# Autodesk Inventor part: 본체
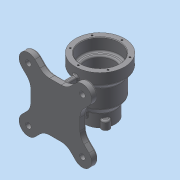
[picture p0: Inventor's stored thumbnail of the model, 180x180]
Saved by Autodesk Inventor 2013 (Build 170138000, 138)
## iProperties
Created: 2017-03
Part Number: 본체
Material: 일반
Document SubType Name: Modeling
Designer: dgall
Density: 1 g/cm^3
Author: dgall
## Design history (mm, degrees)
sketch "스케치1"
  geometry: L1 (0, 50)-(0, -50); L2 (35, 50)-(35, 27); L3 (35, 27)-(26, 27); L4 (26, 27)-(26, -20); L5 (26, -20)-(17.5, -20); L6 (17.5, -20)-(17.5, -50); L7 (17.5, -50)-(27.5, -50); L8 (27.5, -50)-(27.5, -27); L9 (27.5, -27)-(36, -15); L10 (36, -15)-(36, 19); L11 (36, 19)-(45, 30); L12 (45, 30)-(45, 50); L13 (45, 50)-(35, 50); 2 further points
  constraints: 26 end point, 9 parallel, 2 horizontal alignment, 1 coincident, 1 midpoint, 1 perpendicular, 1 vertical
  dimensions: "d0" = 100 distance of L1.start L1.end; "d1" = 23 distance of L2.start L2.end; "d2" = 47 distance of L3.end L4.end; "d3" = 20 distance of L11.end L12.end; "d4" = 31 vertical distance of L10.end L12.end; "d5" = 65 distance from line of L13 L9.end; "d6" = 23 distance of L7.end L8.end; "d7" = 90 diameter of L12 L1; "d8" = 72 diameter of L10 L1; "d9" = 55 diameter of L8 L1; "d10" = 52 diameter of L4 L1; "d11" = 70 diameter of L2 L1; "d12" = 35 diameter of L6 L1
revolve "회전1" sketch "스케치1" stored, may be unused: angle "d13" = 90 deg
sketch "스케치2"
  geometry: C1 r 45 at (0, 0) reference; 1 further point
  constraints: 1 vertical alignment
  dimensions: "d15" = 40 distance of C1.centre point (0, 40)
hole "구멍1" sketch "스케치2" at (0, 40) diameter "d16" = 3.242; stored, may be unused: countersink angle "d20" = 90 deg, drill point angle "d22" = 118 deg; dims "d17" = 9, "d18" = 4, "d19" = 2, "d21" = 11
sketch "스케치3"
  geometry: C1 r 7 at (0, 27.5); 1 further point
  constraints: 1 centre point, 1 vertical alignment, 1 other
  dimensions: "d26" = 14 diameter of C1
extrude "돌출1" join sketch "스케치3" distance "d27" = 15; taper "d28" = 0 deg
hole "구멍2" diameter "d31" = 3.242; stored, may be unused: countersink angle "d35" = 90 deg, drill point angle "d37" = 118 deg; dims "d29" = 10, "d30" = 10, "d32" = 9, "d33" = 4, "d34" = 2, "d36" = 11
node "작업 평면1"
sketch "스케치4"
  geometry: L1 (-45, 50)-(45, 50) reference; C1 r 5 at (0, 0); 1 further point
  constraints: 1 centre point, 1 midpoint, 1 vertical alignment
  dimensions: "d42" = 10 diameter of C1; "d43" = 50 distance from line of L1 C1.centre
extrude "돌출2" join sketch "스케치4" stored distance "d44" = 15; taper "d45" = 0 deg
node "작업 평면2"
sketch "스케치5"
  geometry: L1 (-45, 45)-(45, 45); L2 (45, 45)-(45, -45); L3 (45, -45)-(-45, -45); L4 (-45, -45)-(-45, 45); 3 further points
  constraints: 8 end point, 2 midpoint, 2 parallel, 2 perpendicular, 1 horizontal, 1 horizontal alignment, 1 vertical alignment
  dimensions: "d47" = 90 distance of L1.start L1.end
extrude "돌출3" join sketch "스케치5" distance "d49" = 12; taper "d50" = 0 deg
sketch "스케치6"
  geometry: L1 (-45, -45)-(45, -45) reference; L2 (45, 45)-(-45, 45) reference; L3 (-45, 45)-(-45, -45) reference; L4 (-61.518, 37.477)-(-45, 20.958); L5 (-37.477, 61.518)-(-20.958, 45); L6 (-49.497, 49.497)-(0, 0); C1 r 5 at (-49.497, 49.497); A1 r 70 centre (0, 0) between (-49.497, 49.497) and (-36.106, 59.97); A2 r 17 centre (-49.497, 49.497) between (-36.106, 59.97) and (-59.97, 36.106); 1 further point
  constraints: 7 point on circle, 6 end point, 3 centre point, 2 coincident, 2 parallel, 2 point on line, 2 tangent
  dimensions: "d51" = 140 diameter of A1; "d52" = 34 diameter of A2; "d54" = 10 diameter of C1; "d55" = 45 deg angle of L1 L6
extrude "돌출4" join sketch "스케치6" distance "d56" = 12; taper "d57" = 0 deg
hole "구멍3" diameter "d63" = 4.134; stored, may be unused: countersink angle "d67" = 90 deg, drill point angle "d69" = 118 deg; dims "d61" = 10, "d62" = 10, "d64" = 40, "d65" = 4, "d66" = 2, "d68" = 11
sketch "스케치7"
  geometry: L1 (-70, -20.958)-(-70, 20.958) reference; L2 (-70, 20.958)-(-70, 37.477) reference; L3 (-70, 37.477)-(-70, 66.497) reference; L4 (-70, -37.477)-(-70, -20.958) reference; L5 (-70, -66.497)-(-70, -37.477) reference; L6 (-45, 30)-(45, 30) reference; L7 (-45, 50)-(45, 50) reference; L8 (-45, 50)-(-45, 30) reference; L9 (-36, 19)-(-36, -15) reference; L10 (-45, 30)-(-36, 19) reference; L11 (-36, -15)-(-27.5, -27) reference; L12 (-7.292, -50)-(-7.292, -35) reference; L13 (-7.292, -35)-(-19.317, -35) reference; L14 (-19.317, -35)-(-19.317, -50) reference; L15 (-19.317, -50)-(-19.317, -50) reference; L16 (-19.317, -50)-(-19.317, -35) reference; L17 (-19.317, -35)-(-7.292, -35) reference; L18 (-7.292, -35)-(-7.292, -50) reference; L19 (26.609, -50)-(-7.292, -50) reference; L20 (26.609, -50)-(26.609, -35) reference; L21 (26.609, -35)-(26.609, -35) reference; L22 (26.609, -35)-(26.609, -50) reference; L23 (-7.292, -50)-(26.609, -50) reference; L24 (-27.5, -27)-(27.5, -27) reference; L25 (-27.5, -27)-(-27.5, -50) reference; L26 (-27.5, -37)-(-70, -37); L27 (-45, 37)-(-70, 37); 3 further points
  constraints: 4 end point, 4 point on line, 2 perpendicular
  dimensions: "d70" = 37 distance from line of L27 point (0, 0); "d71" = 37 distance from line of L26 point (0, 0)
  node "투영된 루프1"
  node "투영된 루프2"
feature "리브1" dims "d72" = 37, "d73" = 8, "d74" = 0, "d75" = 0, "d76" = 1, "d77" = 1
feature "리브2" dims "d78" = 37, "d79" = 8, "d80" = 0, "d81" = 0, "d82" = 1, "d83" = 1
sketch "스케치8"
  geometry: L1 (-20.958, -70)-(-37.477, -70) reference; L2 (20.958, -70)-(-20.958, -70) reference; L3 (37.477, -70)-(20.958, -70) reference; L4 (66.497, -70)-(37.477, -70) reference; L5 (-37.477, -70)-(-66.497, -70) reference; L6 (-4, -70)-(-4, -27.208) reference; L7 (4, -27.208)-(4, -70) reference; L8 (-25, -70)-(-18.14, -31.096); A1 r 36 centre (0, 0) between (4, -35.777) and (-4, -35.777) reference; 3 further points
  constraints: 2 end point, 1 point on circle, 1 point on line
  dimensions: "d85" = 25 horizontal distance of point (0, 0) L8.start; "d86" = 100 deg angle of L1 L8
extrude "돌출5" join sketch "스케치8" stored distance "d87" = 8; taper "d88" = 0 deg
fillet "모깎기1" dims "d89" = 25
fillet "모깎기2" dims "d90" = 3
fillet "모깎기3" dims "d91" = 1
chamfer "모따기1" distance "d92" = 1; stored, may be unused: second distance "d93" = 2, angle "d94" = 45 deg
fillet "모깎기4" dims "d95" = 3
fillet "모깎기5" dims "d96" = 3
fillet "모깎기6" dims "d97" = 3
fillet "모깎기7" dims "d98" = 3
fillet "모깎기8" dims "d99" = 3
fillet "모깎기9" dims "d100" = 3
sketch "스케치9"
  geometry: L1 (10.603, 45)-(-10.603, 45) reference; 2 further points
  constraints: 1 other
  dimensions: "d101" = 35 distance of point (0, 0) point (35, 0); "d102" = 45 distance from line of point (35, 0) L1
feature "엠보싱1" sketch "스케치9" dims "d0" = 100, "d1" = 23, "d2" = 47, "d3" = 20, "d4" = 31, "d5" = 65, "d6" = 23, "d7" = 90, "d8" = 72, "d9" = 55, "d10" = 52, "d11" = 70, "d12" = 35, "d15" = 40, "d103" = 0.5, "d104" = 0
node "솔리드1"
pattern_circular "원형 패턴1" dims angle "d24" = 360 deg
pattern_circular "원형 패턴2" dims angle "d39" = 360 deg
pattern_circular "원형 패턴3" dims angle "d59" = 360 deg
mirror "대칭1"
other parameters: "d46" = -82
